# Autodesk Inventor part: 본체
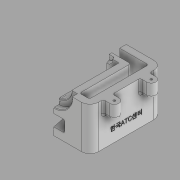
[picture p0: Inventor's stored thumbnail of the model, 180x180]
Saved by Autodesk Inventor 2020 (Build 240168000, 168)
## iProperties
Created: 2022-03
Part Number: 본체
Material: 일반
Document SubType Name: Modeling
Designer: Administrator
Density: 1 g/cm^3
Appearance: 기본값
Author: Administrator
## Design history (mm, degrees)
sketch "스케치1"
  geometry: L1 (-55, 55)-(55, 55); L2 (55, 55)-(55, -55); L3 (55, -55)-(-55, -55); L4 (-55, -55)-(-55, 55); L5 (-55, 55)-(55, -55); L6 (55, 55)-(-55, -55); 1 further point
  constraints: 12 end point, 2 midpoint, 2 parallel, 1 horizontal, 1 perpendicular
  dimensions: "d0" = 110 distance of L2.end L3.end; "d1" = 110 distance of L1.end L2.end
extrude "돌출1" new body sketch "스케치1" distance "d2" = 65; taper "d3" = 0 deg
sketch "스케치2"
  geometry: L1 (-73.452, 28)-(83.043, 28); L2 (55, 55)-(-55, 55) reference; L3 (-65, 35)-(-55, 35); L4 (-65, 21)-(-55, 21); L5 (-73.452, -28)-(83.043, -28); L6 (-65, 61.443)-(-65, 7.688); L7 (-55, 55)-(-55, -55) reference; L8 (0, 55)-(0, 0); L9 (65, 35)-(55, 35); L10 (65, 21)-(55, 21); L11 (-55, 0)-(32.738, 0); L12 (-65, -35)-(-55, -35); L13 (-65, -21)-(-55, -21); L14 (65, -21)-(55, -21); L15 (65, -35)-(55, -35); L16 (55, -55)-(55, 55) reference; L17 (-55, 35)-(-55, 21); L18 (-55, -21)-(-55, -35); L19 (55, 35)-(55, 21); L20 (55, -21)-(55, -35); A1 r 7 centre (-65, 28) between (-65, 35) and (-65, 21); A2 r 7 centre (65, 28) between (65, 21) and (65, 35); A3 r 7 centre (-65, -28) between (-65, -21) and (-65, -35); A4 r 7 centre (65, -28) between (65, -35) and (65, -21); 2 further points
  constraints: 34 end point, 15 symmetric about line, 8 point on circle, 6 point on line, 5 horizontal, 4 centre point, 4 collinear, 2 midpoint, 2 vertical, 3 other
  dimensions: "d4" = 27 distance between parallel lines of L1 L2; "d7" = 56 distance between parallel lines of L5 L1; "d9" = 7 radius of A1; "d10" = 10 distance between parallel lines of L6 L7
extrude "돌출2" join sketch "스케치2" distance "d11" = 20; taper "d12" = 0 deg
sketch "스케치3"
  geometry: A1 r 7 centre (65, 28) between (65, 21) and (65, 35) reference; A2 r 7 centre (65, -28) between (65, -35) and (65, -21) reference; A3 r 7 centre (-65, 28) between (-65, 35) and (-65, 21) reference; A4 r 7 centre (-65, -28) between (-65, -21) and (-65, -35) reference; 5 further points
  constraints: 4 coincident
hole "구멍1" sketch "스케치3" at (65, 28), (65, -28), (-65, 28), (-65, -28) diameter "d13" = 3.242; stored, may be unused: countersink angle "d17" = 90 deg, drill point angle "d19" = 118 deg; dims "d14" = 9, "d15" = 4, "d16" = 2, "d18" = 11
sketch "스케치4"
  geometry: L1 (-41.947, -44.668)-(-41.947, 45); L2 (-41.947, 45)-(43.822, 45); L3 (43.822, 45)-(43.822, -44.668); L4 (43.822, -44.668)-(28.822, -44.668); L5 (28.822, -44.668)-(28.822, 33); L6 (28.822, 33)-(-26.947, 33); L7 (-26.947, 33)-(-26.947, -44.668); L8 (-26.947, -44.668)-(-41.947, -44.668); L9 (55, 55)-(-55, 55) reference; 1 further point
  constraints: 16 end point, 7 perpendicular, 1 point on line, 1 vertical
  dimensions: "d20" = 15 distance of L7.end L1.start; "d21" = 15 distance of L3.end L4.end; "d22" = 12 distance between parallel lines of L6 L2; "d84" = 22 distance between parallel lines of L6 L9
extrude "돌출3" cut sketch "스케치4" extent not by distance; stored distance "d23" = 60; taper "d24" = 0 deg
fillet "모깎기1" dims "d25" = 13
fillet "모깎기2" dims "d26" = 3
sketch "스케치5"
  geometry: L1 (0, 65)-(84, 65) reference; C1 r 28 at (42, 65); 1 further point
  constraints: 1 centre point, 1 midpoint
  dimensions: "d27" = 28 radius of C1
extrude "돌출4" cut sketch "스케치5" distance "d28" = 8; taper "d29" = 0 deg
sketch "스케치6"
  geometry: C1 r 19 at (42, 64.741); 1 further point
  constraints: 1 centre point
  dimensions: "d30" = 19 radius of C1
extrude "돌출5" cut sketch "스케치6" distance "d31" = 72; taper "d32" = 0 deg
node "작업 평면1"
sketch "스케치7"
  geometry: L1 (-25.822, -33)-(23.947, -33) reference; L2 (9.809, -25)-(7.5, -29); L3 (7.5, -29)-(0, -29); L4 (0, -29)-(0, -25); L5 (9.809, -25)-(0, -25); L6 (18.998, -25)-(-18.998, -25) reference; 2 further points
  constraints: 8 end point, 2 midpoint, 1 horizontal, 1 parallel, 1 perpendicular
  dimensions: "d34" = 30 deg angle of L4 L2; "d35" = 7.5 distance of L2.end L3.end; "d36" = 4 distance between parallel lines of L5 L3
revolve "회전1" sketch "스케치7" stored, may be unused: angle "d37" = 90 deg
fillet "모깎기3" dims "d38" = 1
chamfer "모따기1" distance "d39" = 1; stored, may be unused: second distance "d40" = 2, angle "d41" = 60 deg
sketch "스케치8"
  geometry: L1 (62.741, -19)-(28.006, -19); L2 (28.006, -19)-(28.006, 19); L3 (28.006, 19)-(62.741, 19); L4 (62.741, 19)-(62.741, -19); L5 (65, 46)-(65, 46) reference; L6 (65, -24)-(65, 46) reference; L7 (65, -24)-(65, -24) reference; L8 (65, 46)-(65, -24) reference; L9 (65, -24)-(65, -25) reference; L10 (65, -25)-(65, -25) reference; L11 (65, -25)-(65, -24) reference; L12 (65, -24)-(65, -24) reference; L13 (65, -25)-(65, -25) reference; L14 (65, -25)-(65, -25) reference; L15 (45.741, 46)-(45.741, -24) reference; L16 (65, -24)-(65, 46) reference; L17 (46.741, -25)-(65, -25) reference; L18 (65, 55)-(0, 55) reference; A1 r 1 centre (46.741, -24) between (45.741, -24) and (46.741, -25) reference; 3 further points
  constraints: 8 end point, 2 parallel, 1 horizontal, 1 perpendicular
  dimensions: "d42" = 6 distance between parallel lines of L17 L1; "d43" = 38 distance between parallel lines of L3 L1; "d46" = 34 diameter of L4 L15
revolve "회전2" sketch "스케치8" stored, may be unused: angle "d45" = 90 deg
sketch "스케치9" dims "d47" = 46
  geometry: L1 (35.077, 65)-(48.923, 65) reference; 3 further points
  constraints: 1 midpoint, 1 vertical alignment, 2 other
hole "구멍2" sketch "스케치9" at (42, 42) diameter "d48" = 3.242; stored, may be unused: countersink angle "d52" = 90 deg, drill point angle "d54" = 118 deg; dims "d49" = 9, "d50" = 4, "d51" = 2, "d53" = 11
sketch "스케치10"
  geometry: L1 (25, 27.082)-(59, 27.082); L2 (59, 27.082)-(59, 10.082); L3 (59, 10.082)-(25, 10.082); L4 (25, 10.082)-(25, 27.082); L5 (0, 0)-(84, 0) reference; 3 further points
  constraints: 8 end point, 2 midpoint, 2 parallel, 1 horizontal, 1 perpendicular, 1 vertical alignment
  dimensions: "d55" = 34 distance of L2.end L3.end; "d56" = 17 distance of L1.end L2.end
sketch "스케치11"
  geometry: L1 (30, -33)-(12.007, 34.15); L2 (12.007, 34.15)-(0, 34.15); L3 (0, 42)-(0, -42) reference; L4 (65, 55)-(0, 55) reference; L5 (0, 42)-(0, 55) reference; L6 (0, -55)-(0, -42) reference; L7 (11.597, 55)-(23.244, 11.533); L8 (30, -33)-(0, -33); 4 further points
  constraints: 8 end point, 3 point on line, 1 horizontal, 1 parallel, 1 perpendicular, 2 other
  dimensions: "d57" = 75 deg angle to the sketch x axis of L1; "d58" = 5 distance between parallel lines of L7 L1; "d85" = 30 distance from line of L1.start L3
extrude "돌출6" cut sketch "스케치11" stored distance "d59" = 60; taper "d60" = 0 deg
fillet "모깎기4" dims "d61" = 3
fillet "모깎기5" dims "d66" = 3
sketch "스케치13"
  geometry: L1 (12.603, 31.926)-(29.404, -30.776) reference; L2 (11.597, 55)-(31.425, -19); L3 (29.197, 55)-(49.025, -19); L4 (65, 55)-(0, 55) reference; L5 (28.741, -19)-(28.741, 19) reference; L6 (53.346, -19)-(28.741, -19) reference; 3 further points
  constraints: 4 end point, 4 point on line, 2 parallel
  dimensions: "d68" = 5 distance between parallel lines of L1 L2; "d69" = 17 distance between parallel lines of L2 L3
extrude "돌출8" cut sketch "스케치13" stored distance "d70" = 34; taper "d71" = 0 deg
fillet "모깎기7" dims "d72" = 3
sketch "스케치14"
  geometry: L1 (-90, 20)-(-90, -45) reference; L2 (-77, -45)-(7, -45) reference; 2 further points
  constraints: 1 other
  dimensions: "d73" = 55 distance from line of point (-35, -25) L1; "d74" = 20 distance from line of L2 point (-35, -25)
feature "엠보싱1" sketch "스케치14" dims "d0" = 110, "d1" = 110, "d4" = 27, "d7" = 56, "d9" = 7, "d10" = 10, "d75" = 0.5, "d76" = 0
fillet "모깎기8" dims "d77" = 3
fillet "모깎기9" dims "d78" = 3
fillet "모깎기10" dims "d83" = 3
node "솔리드1"
node "투영된 루프1"
node "투영된 루프2"
node "투영된 루프3"
feature "A9D066F2-1C7D-4E18-AEED-F7BC21143FA4" dims "d13" = 3.242, "d14" = 9, "d15" = 4, "d16" = 2, "d17" = 90 deg, "d18" = 11, "d19" = 118 deg
other parameters: "d33" = 65, "d62" = 5, "d63" = 17
